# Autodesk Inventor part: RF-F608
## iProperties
Manager: Dr.-Ing. Roland Schröder
Company: Das Entwicklungsbüro
Category: Katalog
Created: 2009-01
Part Number: RF-F608
Material: ---
Document SubType Name: Blech
Designer: R.Schröder
Surface Area: 5.66315 cm^2
Volume: 0.189002 cm^3
Description: Flachsteckhülse
Sheet Metal Rule: normal
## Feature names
1. Verriegelungsbuckel [Extrusion]
2. Heckansatz [Extrusion]
3. Klemmschale [Extrusion]
4. Erhebung1
5. Klemmflügel [Extrusion]
6. Farbrhülse [Extrusion]
7. Grobblech1
8. Biegung1
